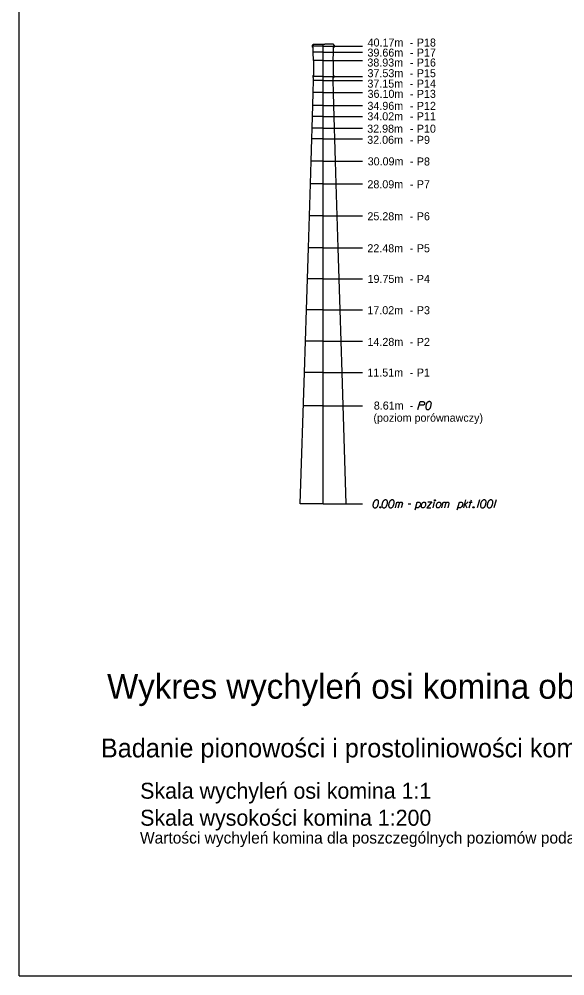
# Model space of a CAD drawing. Extents: x 138 to 6653, y -177 to 1520.
# Drawn here: x 345.89 to 356.39, y 2.29 to 20.71 of the extents above; entities that cross this region are included whole.
import ezdxf

# ---------------------------------------------------------------- set-up
doc = ezdxf.new("R2010")
doc.units = 0
doc.layers.add('Opisy', color=7, linetype='Continuous')
doc.layers.add('Ramka do drukowania', color=7, linetype='Continuous')

msp = doc.modelspace()

# ---------------------------------------------------------------- linework, layer by layer
at = {"layer": 'Opisy'}
for p, q in [((351.532, 20.204), (351.532, 20.185)), ((351.548, 20.204), (351.532, 20.204)), ((351.745, 20.185), (351.532, 20.185)), ((351.532, 20.185), (351.532, 20.166)), ((351.548, 20.166), (351.532, 20.166)), ((351.548, 20.222), (351.548, 20.204)), ((351.548, 20.222), (351.775, 20.222)), ((351.548, 20.072), (351.548, 20.166)), ((351.745, 11.376), (351.745, 20.222)), ((351.745, 20.185), (352.498, 20.185)), ((351.941, 20.222), (351.775, 20.222)), ((351.941, 20.222), (351.941, 20.204)), ((351.941, 20.204), (351.957, 20.204)), ((351.941, 20.166), (351.957, 20.166)), ((351.941, 20.072), (351.941, 20.166)), ((351.957, 20.204), (351.957, 20.185)), ((351.957, 20.185), (351.957, 20.166)), ((351.745, 20.072), (351.548, 20.072)), ((351.555, 19.912), (351.548, 20.072)), ((351.745, 19.912), (351.555, 19.912)), ((351.555, 19.912), (351.555, 19.624)), ((351.745, 20.072), (352.498, 20.072)), ((351.745, 19.912), (352.498, 19.912)), ((351.934, 19.912), (351.941, 20.072)), ((351.934, 19.912), (351.934, 19.624)), ((351.542, 19.624), (351.542, 19.605)), ((351.542, 19.624), (351.555, 19.624)), ((351.745, 19.605), (351.542, 19.605)), ((351.542, 19.605), (351.542, 19.586)), ((351.557, 19.586), (351.542, 19.586)), ((351.555, 19.522), (351.557, 19.586)), ((351.745, 19.605), (352.498, 19.605)), ((351.934, 19.522), (351.933, 19.586)), ((351.933, 19.586), (351.947, 19.586)), ((351.947, 19.624), (351.934, 19.624)), ((351.947, 19.624), (351.947, 19.605)), ((351.947, 19.605), (351.947, 19.586)), ((351.548, 19.291), (351.555, 19.522)), ((351.745, 19.522), (351.555, 19.522)), ((351.745, 19.522), (352.498, 19.522)), ((351.941, 19.291), (351.934, 19.522)), ((351.542, 19.041), (351.548, 19.291)), ((351.745, 19.291), (351.548, 19.291)), ((351.745, 19.291), (352.498, 19.291)), ((351.947, 19.041), (351.941, 19.291)), ((351.535, 18.835), (351.542, 19.041)), ((351.745, 19.041), (351.542, 19.041)), ((351.745, 19.041), (352.498, 19.041)), ((351.954, 18.835), (351.947, 19.041)), ((351.53, 18.607), (351.535, 18.835)), ((351.745, 18.835), (351.535, 18.835)), ((351.745, 18.835), (352.498, 18.835)), ((351.96, 18.607), (351.954, 18.835)), ((351.522, 18.405), (351.53, 18.607)), ((351.745, 18.607), (351.53, 18.607)), ((351.745, 18.607), (352.498, 18.607)), ((351.967, 18.405), (351.96, 18.607)), ((351.51, 17.973), (351.522, 18.405)), ((351.745, 18.405), (351.522, 18.405)), ((351.745, 18.405), (352.498, 18.405)), ((351.979, 17.973), (351.967, 18.405)), ((351.497, 17.535), (351.51, 17.973)), ((351.745, 17.973), (351.51, 17.973)), ((351.745, 17.973), (352.498, 17.973)), ((351.992, 17.535), (351.979, 17.973)), ((351.479, 16.918), (351.497, 17.535)), ((351.745, 17.535), (351.497, 17.535)), ((351.745, 17.535), (352.498, 17.535)), ((352.01, 16.918), (351.992, 17.535)), ((351.46, 16.305), (351.479, 16.918)), ((351.745, 16.918), (351.479, 16.918)), ((351.745, 16.918), (352.498, 16.918)), ((352.03, 16.305), (352.01, 16.918)), ((351.441, 15.706), (351.46, 16.305)), ((351.745, 16.305), (351.46, 16.305)), ((351.745, 16.305), (352.498, 16.305)), ((352.048, 15.706), (352.03, 16.305)), ((351.422, 15.108), (351.441, 15.706)), ((351.745, 15.706), (351.441, 15.706)), ((351.745, 15.706), (352.498, 15.706)), ((352.067, 15.108), (352.048, 15.706)), ((351.404, 14.506), (351.422, 15.108)), ((351.745, 15.108), (351.422, 15.108)), ((351.745, 15.108), (352.498, 15.108)), ((352.086, 14.506), (352.067, 15.108)), ((351.384, 13.9), (351.404, 14.506)), ((351.745, 14.506), (351.404, 14.506)), ((351.745, 14.506), (352.498, 14.506)), ((352.105, 13.9), (352.086, 14.506)), ((351.301, 11.376), (351.384, 13.9)), ((351.745, 13.9), (351.384, 13.9)), ((351.745, 13.9), (352.498, 13.9)), ((352.188, 11.376), (352.105, 13.9)), ((351.745, 13.263), (351.363, 13.263)), ((351.745, 13.263), (352.498, 13.263)), ((351.745, 11.376), (351.301, 11.376)), ((351.745, 11.376), (352.498, 11.376))]:
    msp.add_line(p, q, dxfattribs=at)
for points in [[(353.567, 13.189), (353.608, 13.343), (353.66, 13.343), (353.668, 13.342), (353.671, 13.34), (353.679, 13.337), (353.683, 13.333), (353.687, 13.328), (353.691, 13.322), (353.693, 13.314), (353.694, 13.306), (353.693, 13.3), (353.692, 13.295), (353.689, 13.291), (353.687, 13.287), (353.683, 13.282), (353.679, 13.278), (353.675, 13.276), (353.669, 13.274), (353.663, 13.272), (353.59, 13.272)], [(353.788, 13.343), (353.785, 13.343), (353.778, 13.342), (353.773, 13.34), (353.77, 13.339), (353.764, 13.337), (353.756, 13.333), (353.75, 13.329), (353.744, 13.325), (353.74, 13.32), (353.737, 13.314), (353.733, 13.308), (353.73, 13.3), (353.727, 13.295), (353.725, 13.288), (353.721, 13.276), (353.717, 13.258), (353.715, 13.243), (353.715, 13.23), (353.716, 13.22), (353.721, 13.209), (353.725, 13.203), (353.731, 13.196), (353.738, 13.191), (353.742, 13.19), (353.749, 13.189), (353.755, 13.189), (353.765, 13.19), (353.773, 13.192), (353.779, 13.196), (353.788, 13.202), (353.791, 13.206), (353.796, 13.21), (353.8, 13.215), (353.802, 13.219), (353.805, 13.225), (353.806, 13.227), (353.808, 13.234), (353.811, 13.241), (353.813, 13.248), (353.815, 13.253), (353.816, 13.257), (353.817, 13.261), (353.819, 13.272), (353.821, 13.278), (353.822, 13.285), (353.823, 13.293), (353.824, 13.304), (353.824, 13.308), (353.823, 13.312), (353.822, 13.317), (353.818, 13.325), (353.815, 13.329), (353.811, 13.333), (353.806, 13.337), (353.801, 13.339), (353.798, 13.34), (353.794, 13.342), (353.788, 13.343)], [(352.774, 11.45), (352.772, 11.45), (352.764, 11.449), (352.759, 11.448), (352.756, 11.447), (352.75, 11.444), (352.742, 11.441), (352.736, 11.437), (352.73, 11.432), (352.727, 11.427), (352.723, 11.421), (352.719, 11.415), (352.716, 11.408), (352.713, 11.403), (352.711, 11.396), (352.707, 11.384), (352.704, 11.365), (352.701, 11.351), (352.701, 11.337), (352.702, 11.328), (352.707, 11.317), (352.711, 11.311), (352.717, 11.303), (352.724, 11.299), (352.728, 11.297), (352.735, 11.296), (352.741, 11.296), (352.751, 11.297), (352.759, 11.3), (352.765, 11.303), (352.774, 11.31), (352.778, 11.313), (352.782, 11.318), (352.786, 11.323), (352.789, 11.327), (352.791, 11.333), (352.792, 11.335), (352.795, 11.341), (352.797, 11.348), (352.799, 11.356), (352.801, 11.361), (352.802, 11.364), (352.803, 11.369), (352.805, 11.38), (352.807, 11.386), (352.808, 11.392), (352.809, 11.401), (352.81, 11.412), (352.81, 11.415), (352.809, 11.42), (352.808, 11.425), (352.804, 11.432), (352.801, 11.437), (352.797, 11.441), (352.792, 11.444), (352.787, 11.447), (352.784, 11.448), (352.78, 11.449), (352.774, 11.45)], [(352.945, 11.45), (352.943, 11.45), (352.935, 11.449), (352.931, 11.448), (352.927, 11.447), (352.921, 11.444), (352.914, 11.441), (352.907, 11.437), (352.901, 11.432), (352.898, 11.427), (352.894, 11.421), (352.89, 11.415), (352.887, 11.408), (352.884, 11.403), (352.882, 11.396), (352.878, 11.384), (352.875, 11.365), (352.872, 11.351), (352.872, 11.337), (352.873, 11.328), (352.878, 11.317), (352.882, 11.311), (352.888, 11.303), (352.895, 11.299), (352.899, 11.297), (352.906, 11.296), (352.912, 11.296), (352.922, 11.297), (352.931, 11.3), (352.937, 11.303), (352.945, 11.31), (352.949, 11.313), (352.954, 11.318), (352.957, 11.323), (352.96, 11.327), (352.962, 11.333), (352.963, 11.335), (352.966, 11.341), (352.968, 11.348), (352.971, 11.356), (352.972, 11.361), (352.973, 11.364), (352.974, 11.369), (352.977, 11.38), (352.978, 11.386), (352.979, 11.392), (352.98, 11.401), (352.981, 11.412), (352.981, 11.415), (352.98, 11.42), (352.979, 11.425), (352.975, 11.432), (352.972, 11.437), (352.968, 11.441), (352.963, 11.444), (352.958, 11.447), (352.955, 11.448), (352.951, 11.449), (352.945, 11.45)], [(353.075, 11.45), (353.073, 11.45), (353.065, 11.449), (353.06, 11.448), (353.057, 11.447), (353.051, 11.444), (353.043, 11.441), (353.037, 11.437), (353.031, 11.432), (353.028, 11.427), (353.024, 11.421), (353.02, 11.415), (353.017, 11.408), (353.014, 11.403), (353.012, 11.396), (353.008, 11.384), (353.005, 11.365), (353.002, 11.351), (353.002, 11.337), (353.003, 11.328), (353.008, 11.317), (353.012, 11.311), (353.018, 11.303), (353.025, 11.299), (353.029, 11.297), (353.036, 11.296), (353.042, 11.296), (353.052, 11.297), (353.06, 11.3), (353.066, 11.303), (353.075, 11.31), (353.079, 11.313), (353.083, 11.318), (353.087, 11.323), (353.09, 11.327), (353.092, 11.333), (353.093, 11.335), (353.096, 11.341), (353.098, 11.348), (353.1, 11.356), (353.102, 11.361), (353.103, 11.364), (353.104, 11.369), (353.107, 11.38), (353.108, 11.386), (353.109, 11.392), (353.11, 11.401), (353.111, 11.412), (353.111, 11.415), (353.11, 11.42), (353.109, 11.425), (353.105, 11.432), (353.102, 11.437), (353.098, 11.441), (353.093, 11.444), (353.088, 11.447), (353.085, 11.448), (353.081, 11.449), (353.075, 11.45)], [(353.89, 11.45), (353.896, 11.45), (353.899, 11.448), (353.903, 11.443), (353.903, 11.437), (353.899, 11.432), (353.896, 11.43), (353.89, 11.43), (353.886, 11.432), (353.882, 11.437), (353.882, 11.443), (353.886, 11.448), (353.89, 11.45)], [(354.446, 11.296), (354.487, 11.45)], [(354.554, 11.296), (354.594, 11.45)], [(354.749, 11.45), (354.708, 11.296)], [(354.842, 11.45), (354.84, 11.45), (354.833, 11.449), (354.828, 11.448), (354.824, 11.447), (354.818, 11.444), (354.811, 11.441), (354.805, 11.437), (354.799, 11.432), (354.795, 11.427), (354.791, 11.421), (354.788, 11.415), (354.784, 11.408), (354.782, 11.403), (354.779, 11.396), (354.776, 11.384), (354.772, 11.365), (354.77, 11.351), (354.77, 11.337), (354.771, 11.328), (354.776, 11.317), (354.779, 11.311), (354.785, 11.303), (354.793, 11.299), (354.796, 11.297), (354.804, 11.296), (354.81, 11.296), (354.819, 11.297), (354.828, 11.3), (354.834, 11.303), (354.842, 11.31), (354.846, 11.313), (354.851, 11.318), (354.855, 11.323), (354.857, 11.327), (354.859, 11.333), (354.861, 11.335), (354.863, 11.341), (354.865, 11.348), (354.868, 11.356), (354.869, 11.361), (354.87, 11.364), (354.872, 11.369), (354.874, 11.38), (354.875, 11.386), (354.876, 11.392), (354.878, 11.401), (354.879, 11.412), (354.879, 11.415), (354.878, 11.42), (354.876, 11.425), (354.873, 11.432), (354.869, 11.437), (354.865, 11.441), (354.861, 11.444), (354.856, 11.447), (354.852, 11.448), (354.848, 11.449), (354.842, 11.45)], [(354.972, 11.45), (354.97, 11.45), (354.963, 11.449), (354.958, 11.448), (354.954, 11.447), (354.948, 11.444), (354.941, 11.441), (354.935, 11.437), (354.929, 11.432), (354.925, 11.427), (354.921, 11.421), (354.918, 11.415), (354.914, 11.408), (354.912, 11.403), (354.909, 11.396), (354.906, 11.384), (354.902, 11.365), (354.899, 11.351), (354.899, 11.337), (354.901, 11.328), (354.906, 11.317), (354.909, 11.311), (354.915, 11.303), (354.923, 11.299), (354.926, 11.297), (354.933, 11.296), (354.94, 11.296), (354.949, 11.297), (354.958, 11.3), (354.964, 11.303), (354.972, 11.31), (354.976, 11.313), (354.981, 11.318), (354.984, 11.323), (354.987, 11.327), (354.989, 11.333), (354.99, 11.335), (354.993, 11.341), (354.995, 11.348), (354.998, 11.356), (354.999, 11.361), (355, 11.364), (355.001, 11.369), (355.004, 11.38), (355.005, 11.386), (355.006, 11.392), (355.007, 11.401), (355.009, 11.412), (355.009, 11.415), (355.007, 11.42), (355.006, 11.425), (355.003, 11.432), (354.999, 11.437), (354.995, 11.441), (354.99, 11.444), (354.986, 11.447), (354.982, 11.448), (354.978, 11.449), (354.972, 11.45)], [(355.071, 11.45), (355.029, 11.296)], [(352.838, 11.317), (352.844, 11.317), (352.848, 11.314), (352.852, 11.31), (352.852, 11.303), (352.848, 11.299), (352.844, 11.296), (352.838, 11.296), (352.835, 11.299), (352.831, 11.303), (352.831, 11.31), (352.835, 11.314), (352.838, 11.317)], [(353.132, 11.296), (353.16, 11.407)], [(353.153, 11.378), (353.159, 11.391), (353.165, 11.398), (353.172, 11.403), (353.179, 11.407), (353.184, 11.409), (353.191, 11.409), (353.194, 11.408), (353.199, 11.403), (353.204, 11.397), (353.207, 11.386), (353.208, 11.38), (353.215, 11.391), (353.222, 11.398), (353.229, 11.403), (353.236, 11.407), (353.242, 11.409), (353.249, 11.409), (353.253, 11.408), (353.257, 11.403), (353.261, 11.397), (353.264, 11.386), (353.266, 11.38), (353.245, 11.296)], [(353.188, 11.296), (353.208, 11.38)], [(353.375, 11.374), (353.427, 11.374)], [(353.51, 11.256), (353.551, 11.408)], [(353.547, 11.395), (353.559, 11.404), (353.578, 11.408), (353.592, 11.405), (353.602, 11.398), (353.609, 11.388), (353.614, 11.375), (353.615, 11.363), (353.613, 11.352), (353.609, 11.339), (353.599, 11.324), (353.587, 11.311), (353.569, 11.299), (353.553, 11.296), (353.539, 11.297), (353.523, 11.306)], [(353.683, 11.408), (353.692, 11.408), (353.701, 11.403), (353.711, 11.39), (353.712, 11.384), (353.714, 11.378), (353.714, 11.373), (353.714, 11.354), (353.71, 11.342), (353.704, 11.328), (353.697, 11.316), (353.684, 11.305), (353.674, 11.296), (353.655, 11.296), (353.648, 11.299), (353.641, 11.305), (353.637, 11.311), (353.632, 11.325), (353.632, 11.347), (353.635, 11.354), (353.64, 11.37), (353.644, 11.379), (353.647, 11.384), (353.659, 11.397), (353.671, 11.404), (353.683, 11.408)], [(353.756, 11.41), (353.835, 11.41), (353.734, 11.296), (353.812, 11.296)], [(353.856, 11.296), (353.887, 11.414)], [(353.975, 11.408), (353.983, 11.408), (353.993, 11.403), (354.002, 11.39), (354.004, 11.384), (354.005, 11.378), (354.005, 11.373), (354.005, 11.354), (354.001, 11.342), (353.995, 11.328), (353.988, 11.316), (353.976, 11.305), (353.965, 11.296), (353.947, 11.296), (353.939, 11.299), (353.932, 11.305), (353.928, 11.311), (353.924, 11.325), (353.924, 11.347), (353.926, 11.354), (353.931, 11.37), (353.936, 11.379), (353.938, 11.384), (353.95, 11.397), (353.962, 11.404), (353.975, 11.408)], [(354.026, 11.296), (354.053, 11.407)], [(354.046, 11.378), (354.052, 11.391), (354.058, 11.398), (354.066, 11.403), (354.073, 11.407), (354.078, 11.409), (354.085, 11.409), (354.087, 11.408), (354.092, 11.403), (354.097, 11.397), (354.101, 11.386), (354.102, 11.38), (354.108, 11.391), (354.115, 11.398), (354.123, 11.403), (354.13, 11.407), (354.136, 11.409), (354.142, 11.409), (354.147, 11.408), (354.151, 11.403), (354.154, 11.397), (354.158, 11.386), (354.159, 11.38), (354.138, 11.296)], [(354.081, 11.296), (354.102, 11.38)], [(354.323, 11.256), (354.364, 11.408)], [(354.361, 11.395), (354.373, 11.404), (354.391, 11.408), (354.405, 11.405), (354.415, 11.398), (354.422, 11.388), (354.427, 11.375), (354.429, 11.363), (354.426, 11.352), (354.422, 11.339), (354.413, 11.324), (354.401, 11.311), (354.382, 11.299), (354.367, 11.296), (354.352, 11.297), (354.336, 11.306)], [(354.46, 11.351), (354.533, 11.412)], [(354.475, 11.363), (354.506, 11.296)], [(354.554, 11.408), (354.612, 11.408)], [(354.632, 11.317), (354.638, 11.317), (354.642, 11.314), (354.646, 11.31), (354.646, 11.303), (354.642, 11.299), (354.638, 11.296), (354.632, 11.296), (354.629, 11.299), (354.625, 11.303), (354.625, 11.31), (354.629, 11.314), (354.632, 11.317)]]:
    msp.add_lwpolyline(points, dxfattribs=at)
at = {"layer": 'Ramka do drukowania'}
for q in [(345.893, 31.985), (366.893, 2.285)]:
    msp.add_line((345.893, 2.285), q, dxfattribs=at)

# ---------------------------------------------------------------- texts
at = {"layer": 'Opisy'}
for s, height, p in [('40.17m', 0.1542, (352.597, 20.179)), ('P18', 0.1542, (353.545, 20.179)), ('39.66m', 0.1542, (352.595, 19.985)), ('-', 0.154, (353.408, 20.179)), ('P17', 0.1542, (353.545, 19.985)), ('38.93m', 0.1542, (352.593, 19.794)), ('-', 0.154, (353.409, 19.985)), ('P16', 0.1542, (353.545, 19.794)), ('37.53m', 0.1542, (352.596, 19.589)), ('-', 0.154, (353.412, 19.794)), ('P15', 0.1542, (353.545, 19.589)), ('37.15m', 0.1542, (352.594, 19.388)), ('-', 0.154, (353.408, 19.589)), ('P14', 0.1542, (353.545, 19.388)), ('36.10m', 0.1542, (352.597, 19.191)), ('-', 0.154, (353.408, 19.388)), ('P13', 0.1542, (353.544, 19.191)), ('-', 0.154, (353.409, 19.191)), ('34.96m', 0.1542, (352.594, 18.96)), ('-', 0.154, (353.409, 18.96)), ('P12', 0.1542, (353.545, 18.96)), ('34.02m', 0.1542, (352.593, 18.759)), ('-', 0.154, (353.409, 18.759)), ('P11', 0.1542, (353.544, 18.759)), ('32.98m', 0.1542, (352.59, 18.52)), ('P10', 0.1542, (353.545, 18.52)), ('32.06m', 0.1542, (352.59, 18.306)), ('-', 0.154, (353.409, 18.52)), ('P9', 0.1542, (353.545, 18.306)), ('-', 0.154, (353.409, 18.306)), ('30.09m', 0.1542, (352.599, 17.891)), ('-', 0.154, (353.409, 17.891)), ('P8', 0.1542, (353.545, 17.889)), ('28.09m', 0.1542, (352.594, 17.45)), ('-', 0.154, (353.409, 17.45)), ('P7', 0.1542, (353.544, 17.45)), ('25.28m', 0.1542, (352.594, 16.834)), ('P6', 0.1542, (353.544, 16.834)), ('-', 0.154, (353.408, 16.834)), ('22.48m', 0.1542, (352.593, 16.218)), ('-', 0.154, (353.408, 16.218)), ('P5', 0.1542, (353.545, 16.218)), ('19.75m', 0.1542, (352.596, 15.628)), ('-', 0.154, (353.408, 15.628)), ('P4', 0.1542, (353.545, 15.628)), ('17.02m', 0.1542, (352.593, 15.025)), ('P3', 0.1542, (353.545, 15.025)), ('-', 0.154, (353.408, 15.025)), ('14.28m', 0.1542, (352.595, 14.415)), ('P2', 0.1542, (353.544, 14.415)), ('-', 0.154, (353.408, 14.415)), ('11.51m', 0.1542, (352.593, 13.825)), ('-', 0.154, (353.408, 13.825)), ('P1', 0.1542, (353.545, 13.825)), ('8.61m', 0.1542, (352.717, 13.189)), ('(poziom porównawczy)', 0.15416, (352.71, 12.955)), ('-', 0.154, (353.408, 13.189)), ('Wykres wychyleń osi komina obserwowanych ze stanowiska 1001', 0.47516, (347.585, 7.621)), ('Badanie pionowości i prostoliniowości komina zakładu ceramicznego "Ceramika Stróże"', 0.36281, (347.466, 6.492)), ('Skala wychyleń osi komina 1:1', 0.30766, (348.221, 5.696)), ('Skala wysokości komina 1:200', 0.30766, (348.221, 5.176)), ('Wartości wychyleń komina dla poszczególnych poziomów podano w milimetrach', 0.22315, (348.218, 4.833))]:
    msp.add_text(s, height=height, dxfattribs=at).set_placement(p)

doc.saveas('drawing.dxf')
